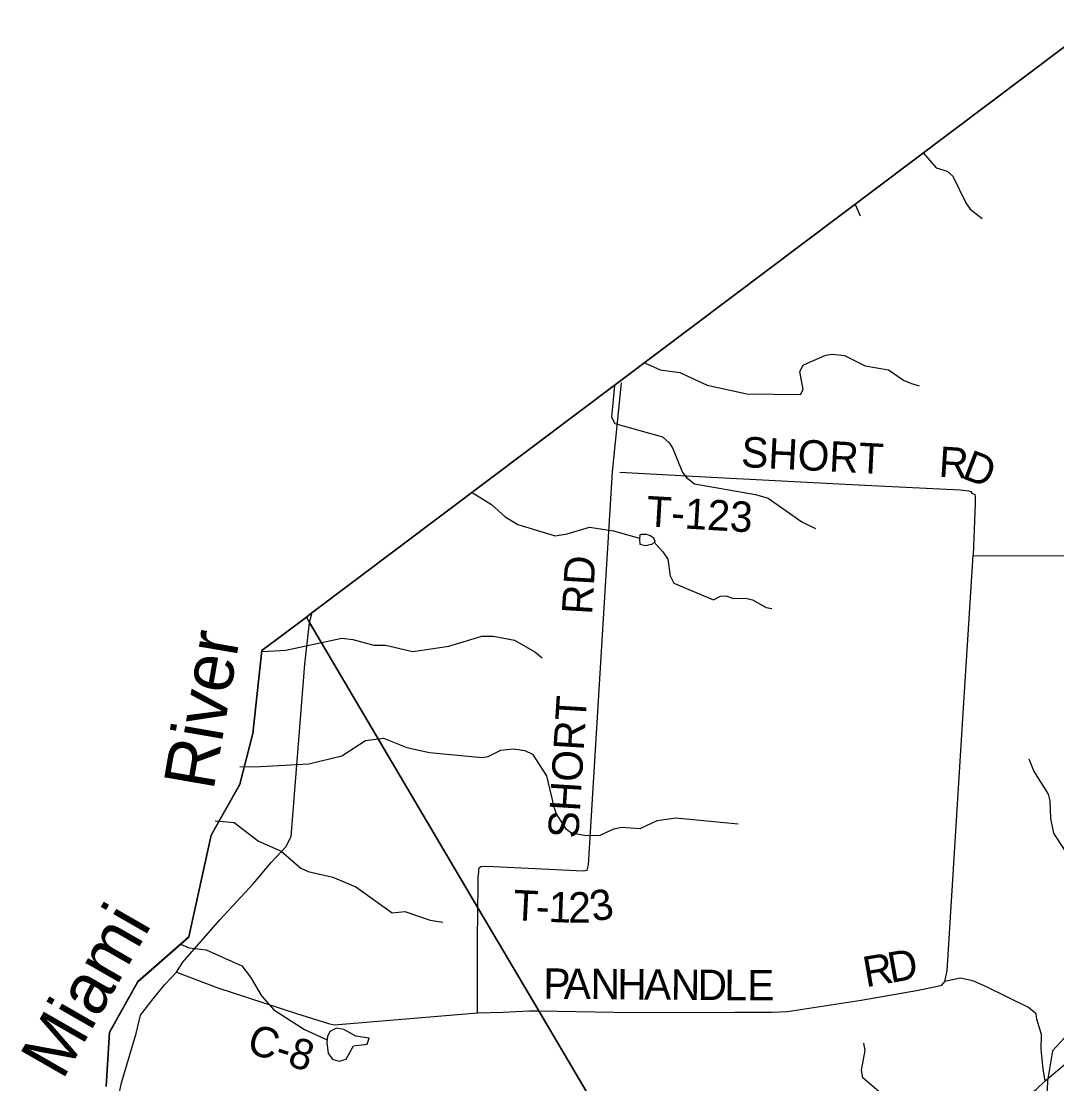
# Model space of a CAD drawing. Extents: x 1525783 to 1900577, y 218250 to 627376.
# Drawn here: x 1602357 to 1612574, y 458283 to 468763 of the extents above; entities that cross this region are included whole.
import ezdxf

# ---------------------------------------------------------------- set-up
doc = ezdxf.new("R2010")
doc.units = 0
for name, color, linetype in [('GM_X_Adjacent_County', 7, 'Continuous'), ('GM_X_County', 7, 'Continuous'), ('GM_X_County_Road', 7, 'Continuous'), ('GM_X_County_Road_Text', 7, 'Continuous'), ('GM_X_Major_River', 7, 'Continuous'), ('GM_X_Major_River_Text', 7, 'Continuous'), ('GM_X_Minor_Lake', 7, 'Continuous'), ('GM_X_Minor_River', 7, 'Continuous'), ('GM_X_State_Route', 7, 'Continuous'), ('GM_X_Township', 7, 'Continuous'), ('GM_X_Township_Road', 7, 'Continuous'), ('GM_X_Township_Road_Text', 7, 'Continuous')]:
    doc.layers.add(name, color=color, linetype=linetype)

msp = doc.modelspace()

# ---------------------------------------------------------------- linework, layer by layer
at = {"layer": 'GM_X_Adjacent_County'}
msp.add_lwpolyline([(1612987, 468763), (1608261, 465210), (1605211, 462917), (1605170, 462886), (1604731, 462556), (1604641, 461739), (1604515, 461237), (1604229, 460736), (1604010, 459731), (1603508, 459291), (1603228, 458790), (1603196, 458254)], dxfattribs=at)
at = {"layer": 'GM_X_County'}
msp.add_lwpolyline([(1603196, 458254), (1603228, 458790), (1603508, 459291), (1604010, 459731), (1604229, 460736), (1604515, 461237), (1604641, 461739), (1604731, 462556), (1605170, 462886), (1605211, 462917), (1608261, 465210), (1612987, 468763)], dxfattribs=at)
at = {"layer": 'GM_X_County_Road'}
for points in [[(1608202, 458990), (1608203, 458990), (1608370, 458987), (1609398, 458988), (1609760, 458989), (1609917, 458994), (1610645, 459107), (1610906, 459152), (1611190, 459203), (1611367, 459238), (1611441, 459254), (1611469, 459292), (1611494, 459398), (1611652, 461938), (1611750, 463493), (1614078, 463489), (1615942, 464351), (1616894, 464836)], [(1603889, 459384), (1604296, 459229), (1605074, 458977), (1605387, 458878), (1605445, 458863), (1606858, 458983), (1607111, 458990), (1607367, 459003), (1607462, 459002), (1608202, 458990)], [(1609444, 456424), (1609739, 456414), (1609925, 456431), (1610041, 456462), (1610198, 456536), (1610674, 456874), (1610928, 457046), (1611036, 457117), (1611159, 457195), (1611241, 457268), (1611331, 457382), (1611395, 457511), (1611439, 457584), (1611521, 457660), (1611608, 457706), (1611743, 457782), (1612371, 458226), (1612458, 458311), (1613021, 458786)]]:
    msp.add_lwpolyline(points, dxfattribs=at)
at = {"layer": 'GM_X_Major_River'}
msp.add_lwpolyline([(1603199, 458255), (1603231, 458791), (1603511, 459292), (1604013, 459732), (1604233, 460737), (1604518, 461238), (1604644, 461740), (1604734, 462557)], dxfattribs=at)
at = {"layer": 'GM_X_Minor_Lake'}
for points in [[(1608457, 463651), (1608460, 463605), (1608516, 463593), (1608558, 463600), (1608582, 463606), (1608611, 463632), (1608599, 463664), (1608561, 463688), (1608529, 463699), (1608497, 463699), (1608475, 463699)], [(1608475, 463699), (1608459, 463698), (1608457, 463651)], [(1605373, 458688), (1605385, 458580), (1605427, 458524), (1605493, 458505), (1605563, 458524), (1605635, 458657), (1605771, 458672), (1605790, 458731), (1605658, 458753), (1605539, 458817), (1605467, 458832), (1605400, 458798)], [(1605400, 458798), (1605377, 458749), (1605374, 458725), (1605373, 458688)]]:
    msp.add_lwpolyline(points, dxfattribs=at)
at = {"layer": 'GM_X_Minor_River'}
for points in [[(1611259, 467462), (1611384, 467316), (1611492, 467285), (1611549, 467234), (1611676, 466970), (1611721, 466909), (1611838, 466818)], [(1610585, 466955), (1610635, 466844)], [(1608506, 465392), (1608660, 465324), (1608854, 465299), (1609123, 465174), (1609515, 465089), (1610047, 465081), (1610072, 465132), (1610040, 465309), (1610073, 465371), (1610126, 465396), (1610295, 465468), (1610357, 465478), (1610479, 465466), (1610682, 465365), (1610914, 465325), (1611061, 465223), (1611141, 465188), (1611216, 465165)], [(1608211, 465171), (1608182, 464857), (1608215, 464794), (1608684, 464664), (1608751, 464605), (1608781, 464555), (1608882, 464313), (1608919, 464263), (1608999, 464200), (1609600, 464094), (1609728, 464059), (1610057, 463826), (1610195, 463759)], [(1606807, 464115), (1606995, 463996), (1607132, 463876), (1607255, 463798), (1607626, 463686), (1607742, 463708), (1607962, 463772), (1608199, 463737), (1608457, 463663)], [(1608601, 463623), (1608688, 463528), (1608735, 463456), (1608761, 463291), (1608794, 463219), (1609188, 463056), (1609257, 463093), (1609309, 463094), (1609383, 463069), (1609505, 463072), (1609573, 463057), (1609706, 462979), (1609764, 462971)], [(1604735, 462545), (1604967, 462558), (1605520, 462677), (1605628, 462666), (1605837, 462609), (1605952, 462608), (1606221, 462545), (1606574, 462600), (1606900, 462697), (1607014, 462699), (1607224, 462657), (1607425, 462542), (1607496, 462483)], [(1604513, 461413), (1604658, 461408), (1605195, 461437), (1605519, 461517), (1605753, 461667), (1605932, 461693), (1606161, 461598), (1606385, 461549), (1606903, 461501), (1606963, 461512), (1607088, 461573), (1607215, 461585), (1607324, 461570), (1607400, 461533), (1607538, 461321), (1607612, 461013), (1607635, 460945), (1607727, 460802), (1607785, 460759), (1607915, 460735), (1607969, 460732), (1608069, 460735), (1608204, 460798), (1608280, 460813), (1608464, 460801), (1608630, 460879), (1608816, 460905), (1609429, 460845)], [(1612965, 458985), (1612912, 459232), (1612825, 459522), (1612818, 459594), (1612878, 459738), (1612860, 459918), (1612824, 460061), (1612753, 460186), (1612732, 460258), (1612732, 460400), (1612696, 460521), (1612546, 460753), (1612514, 460898), (1612510, 461072), (1612493, 461139), (1612348, 461369), (1612303, 461483)], [(1604270, 460877), (1604457, 460859), (1604697, 460676), (1604920, 460577), (1605116, 460410), (1605188, 460377), (1605430, 460322), (1605657, 460226), (1606018, 459967), (1606140, 459981), (1606390, 459896), (1606518, 459877)], [(1614528, 460511), (1614489, 460421), (1614435, 460085), (1614389, 459918), (1614281, 459771), (1614214, 459733), (1614091, 459701), (1613742, 459609), (1613417, 459479), (1613308, 459384), (1613188, 459245), (1613098, 459120), (1612869, 458888), (1612647, 458731), (1612531, 458608), (1612483, 458310), (1612480, 458228), (1612499, 457963), (1612539, 457792)], [(1603927, 459660), (1604014, 459622), (1604181, 459604), (1604533, 459446), (1604618, 459335), (1604726, 459149), (1604848, 459011), (1605152, 458819), (1605374, 458715)], [(1611085, 457743), (1611027, 457831), (1611002, 457901), (1610891, 458005), (1610863, 458055), (1610845, 458184), (1610661, 458340), (1610648, 458416), (1610684, 458610), (1610671, 458682)]]:
    msp.add_lwpolyline(points, dxfattribs=at)
at = {"layer": 'GM_X_State_Route'}
msp.add_lwpolyline([(1603293, 457999), (1603307, 458107), (1603347, 458293), (1603425, 458559), (1603491, 458780), (1603534, 458958), (1603657, 459120), (1603775, 459261), (1603889, 459384), (1603950, 459481), (1604315, 459898), (1604648, 460258), (1604821, 460464), (1604968, 460620), (1605021, 460720), (1605154, 462420), (1605201, 462832), (1605224, 462918)], dxfattribs=at)
at = {"layer": 'GM_X_Township'}
for points in [[(1613251, 449193), (1608973, 456441), (1607462, 459002), (1606863, 460017), (1605201, 462832), (1605170, 462886), (1605211, 462917), (1608261, 465210), (1612987, 468763)], [(1603196, 458254), (1603228, 458790), (1603508, 459291), (1604010, 459731), (1604229, 460736), (1604515, 461237), (1604641, 461739), (1604731, 462556), (1605170, 462886), (1605201, 462832), (1606863, 460017), (1607462, 459002), (1608973, 456441)]]:
    msp.add_lwpolyline(points, dxfattribs=at)
at = {"layer": 'GM_X_Township_Road'}
for points in [[(1606862, 459978), (1606862, 459980), (1606863, 460017), (1606865, 460206), (1606866, 460320), (1606870, 460370), (1606870, 460402), (1606876, 460414), (1606890, 460426), (1606950, 460430), (1607902, 460382), (1607940, 460391), (1607954, 460441), (1608089, 462655), (1608192, 464317), (1608278, 465195)], [(1608264, 464314), (1609106, 464268), (1610549, 464193), (1611621, 464140), (1611707, 464132), (1611727, 464124), (1611737, 464108), (1611767, 464094), (1611769, 464076), (1611768, 464010), (1611750, 463493)], [(1606858, 458983), (1606859, 459703), (1606862, 459978)], [(1612458, 458311), (1612440, 458425), (1612420, 458623), (1612423, 458769), (1612378, 458921), (1612372, 458971), (1612294, 459034), (1611880, 459240), (1611746, 459299), (1611622, 459324), (1611469, 459292)]]:
    msp.add_lwpolyline(points, dxfattribs=at)

# ---------------------------------------------------------------- texts
at = {"layer": 'GM_X_County_Road_Text'}
for s, rotation, p in [('R', 9.8922, (1610691, 459234)), ('D', 10.2002, (1610936, 459276)), ('P', 359.5486, (1607507, 459121)), ('A', 359.5523, (1607709, 459120)), ('N', 359.5523, (1607973, 459118)), ('H', 359.5483, (1608237, 459115)), ('A', 359.5523, (1608501, 459113)), ('N', 359.5523, (1608765, 459111)), ('D', 359.5483, (1609029, 459109)), ('L', 359.563, (1609293, 459107)), ('E', 359.849, (1609519, 459105)), ('C-8', 342.2913, (1604569, 458596))]:
    msp.add_text(s, height=300, rotation=rotation, dxfattribs=at).set_placement(p)
at = {"layer": 'GM_X_Major_River_Text'}
for s, rotation, p in [('River', 80.1789, (1604252, 461166)), ('Miami', 60.1802, (1602763, 458309))]:
    msp.add_text(s, height=500, rotation=rotation, dxfattribs=at).set_placement(p)
at = {"layer": 'GM_X_Township_Road_Text'}
for s, rotation, p in [('SHORT', 357.0749, (1609455, 464367)), ('R', 356.3874, (1611404, 464270)), ('D', 339.17, (1611627, 464260)), ('T-123', 356.6342, (1608518, 463782)), ('RD', 86.5466, (1607989, 462905)), ('SHORT', 86.4371, (1607852, 460697)), ('T', 357.0288, (1607204, 459897)), ('1', 357.9377, (1607556, 459879)), ('2', 0.3289, (1607754, 459872)), ('3', 10.9944, (1608000, 459879)), ('-', 357.1974, (1607429, 459885))]:
    msp.add_text(s, height=300, rotation=rotation, dxfattribs=at).set_placement(p)

doc.saveas('drawing.dxf')
